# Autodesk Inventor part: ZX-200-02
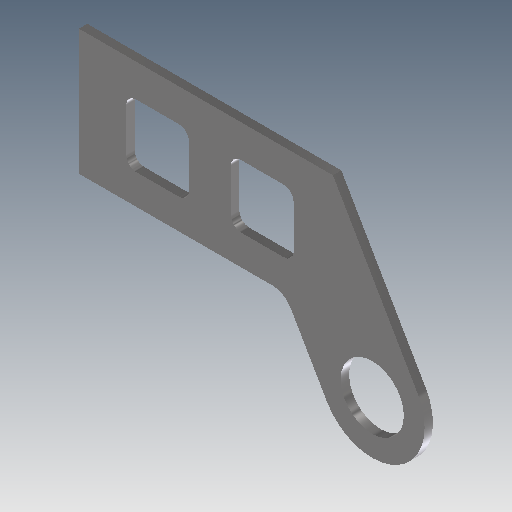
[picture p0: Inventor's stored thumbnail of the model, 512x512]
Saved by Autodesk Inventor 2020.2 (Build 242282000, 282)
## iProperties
Created: 2015-11
Part Number: ZX-200-02
Material: Stal, miękka
Document SubType Name: Modeling
Designer: F.Stasiak
Density: 7.85 g/cm^3
Appearance: Częściowo polerowany
Mass: 2040.73 g
Surface Area: 777.368 cm^2
Volume: 259.966 cm^3
Catalog Web Link: www.expertbooks.pl
Manager: www.cadconsulting.pl
Company: Fabian Stasiak CAD Consulting
Author: F.Stasiak
Subject: Zbiór ćwiczeń. Autodesk Inventor 2020. Kurs Professional
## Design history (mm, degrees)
sketch "Szkic1"
  geometry: L1 (0, 0)-(0, 120); L2 (0, 120)-(242.472, 120); L3 (242.472, 120)-(323.301, -20); L4 (236.699, -70)-(196.284, 0); L5 (196.284, 0)-(0, 0); C1 r 30.15 at (280, -45); A1 r 50 centre (280, -45) between (236.699, -70) and (323.301, -20)
  constraints: 10 end point, 2 centre point, 2 parallel, 2 point on circle, 2 tangent, 1 coincident, 1 perpendicular, 1 vertical
  dimensions: "d0" = 120 distance of L1.start L1.end; "d1" = 50 radius of A1; "d2" = 120 deg angle of L5 L4; "d3" = 45 distance from line of L5 A1.centre; "d4" = 280 distance from line of A1.centre L1; "d5" = 60.3 diameter of C1
extrude "Wyciągnięcie proste1" new body sketch "Szkic1" stored distance "d6" = 8; taper "d7" = 0 deg
sketch "Szkic2"
  geometry: L1 (205, 79.288)-(205, 38.188) reference; L2 (154.45, 88.738)-(195.55, 88.738) reference; L3 (145, 38.188)-(145, 79.288) reference; L4 (195.55, 28.738)-(154.45, 28.738) reference; L5 (54.45, 88.738)-(95.55, 88.738) reference; L6 (45, 38.188)-(45, 79.288) reference; L7 (95.55, 28.738)-(54.45, 28.738) reference; L8 (105, 79.288)-(105, 38.188) reference; A1 r 9.45 centre (195.55, 38.188) between (195.55, 28.738) and (205, 38.188) reference; A2 r 9.45 centre (195.55, 79.288) between (205, 79.288) and (195.55, 88.738) reference; A3 r 9.45 centre (154.45, 79.288) between (154.45, 88.738) and (145, 79.288) reference; A4 r 9.45 centre (154.45, 38.188) between (145, 38.188) and (154.45, 28.738) reference; A5 r 9.45 centre (54.45, 79.288) between (54.45, 88.738) and (45, 79.288) reference; A6 r 9.45 centre (54.45, 38.188) between (45, 38.188) and (54.45, 28.738) reference; A7 r 9.45 centre (95.55, 38.188) between (95.55, 28.738) and (105, 38.188) reference; A8 r 9.45 centre (95.55, 79.288) between (105, 79.288) and (95.55, 88.738) reference; 1 further point
extrude "Wyciągnięcie proste2" cut sketch "Szkic2" extent not by distance; stored distance "d9" = 12; taper "d10" = 0 deg
fillet "Zaokrąglenie2" dims "d11" = 20
node "Bryła1"
node "Odniesienie18"
node "Odniesienie19"
node "Odniesienie20"
node "Odniesienie21"
node "Odniesienie22"
node "Odniesienie23"
node "Odniesienie24"
node "Odniesienie25"
node "Odniesienie26"
node "Odniesienie27"
node "Odniesienie28"
node "Odniesienie29"
node "Odniesienie30"
node "Odniesienie31"
node "Odniesienie32"
node "Odniesienie33"
